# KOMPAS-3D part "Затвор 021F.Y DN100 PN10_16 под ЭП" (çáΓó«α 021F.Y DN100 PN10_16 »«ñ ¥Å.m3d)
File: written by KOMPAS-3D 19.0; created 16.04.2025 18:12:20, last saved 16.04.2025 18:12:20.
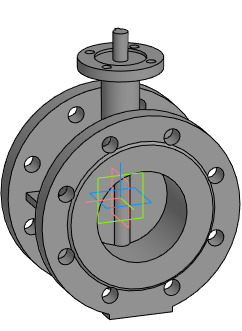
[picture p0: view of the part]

Document properties: Автор: Евгений; Полное имя файла: E:\Dendor Работа Сачек\3D для проекитирвщиков\1.6 Тип 021F.Y Затвор дисковый поворотный фланцевый\stp_Тип 021F.Y Затвор  DN40 PN10_16 под ЭП\Затвор 021F.Y DN100 PN10_16 под ЭП.m3d

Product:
- Part/product: Затвор 021F.Y DN100 PN10_16 под ЭП

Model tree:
1. Операция без истории:1  (labels: Затвор 021F.Y DN100 PN10_16 под ЭП)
